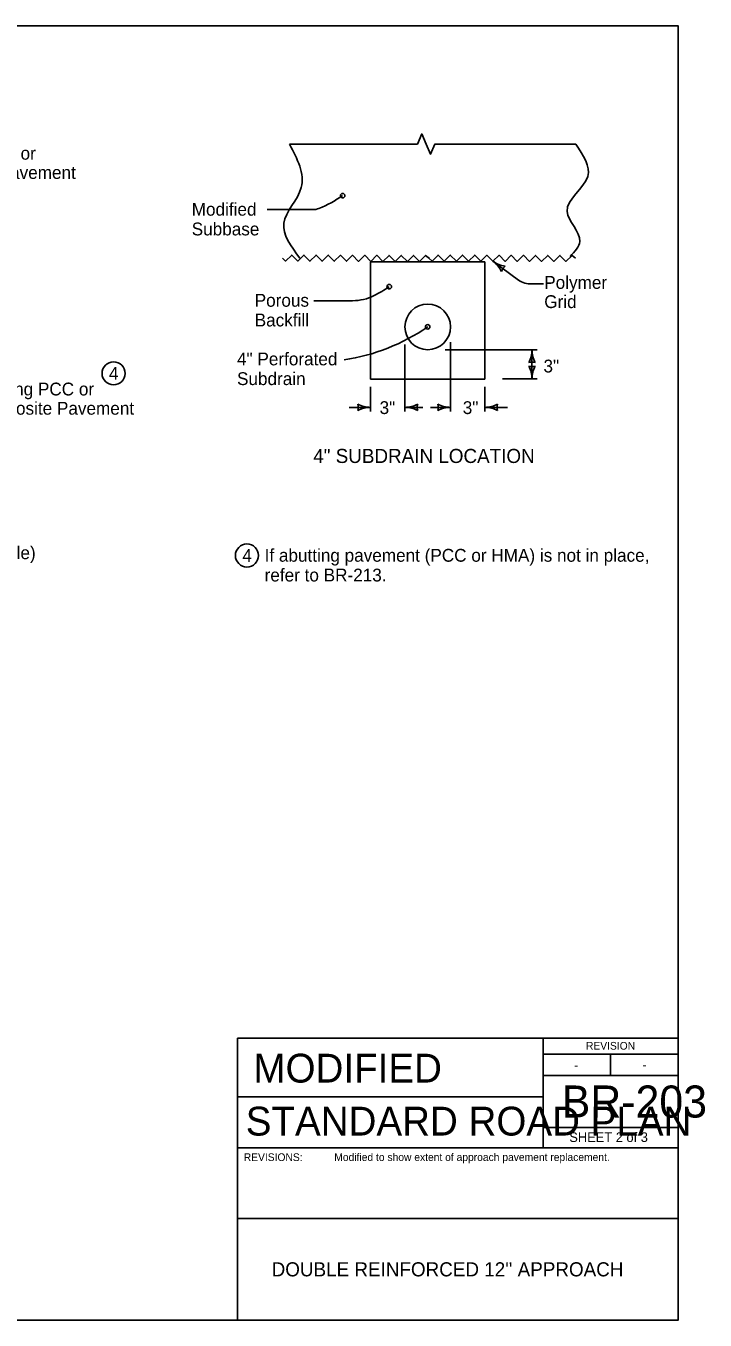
# Model space of a CAD drawing. Extents: x 8925 to 81668, y 4369 to 11918.
# Drawn here: x 15849 to 16910, y 7924 to 9944 of the extents above; entities that cross this region are included whole.
import ezdxf

# ---------------------------------------------------------------- set-up
doc = ezdxf.new("R2010")
doc.units = 0
for name, color, linetype in [('dsnCellElements', 7, 'Continuous'), ('dsnNonPlotable', 7, 'Continuous'), ('dsnShtPlotShapeBatchPrint', 7, 'Continuous'), ('dsnStdBorder', 7, 'Continuous'), ('dsnStdLabel', 7, 'Continuous'), ('Level 1', 7, 'Continuous'), ('Level 3', 7, 'Continuous'), ('Level 5', 7, 'Continuous'), ('SheetBorder', 7, 'Continuous')]:
    doc.layers.add(name, color=color, linetype=linetype)

msp = doc.modelspace()

# ---------------------------------------------------------------- linework, layer by layer
at = {"layer": 'dsnShtPlotShapeBatchPrint'}
for p, q in [((16618.4, 9547), (16578.5, 9576.7)), ((16639, 9541.2), (16657.3, 9541.2)), ((16441, 9446.8), (16441, 9342.1)), ((16504, 9438.6), (16647.5, 9438.6)), ((16512.3, 9450.2), (16512.3, 9342.1)), ((16639.3, 9438.6), (16639.3, 9393)), ((16593.1, 9393), (16647.5, 9393)), ((16387.5, 9380.7), (16387.5, 9342.1)), ((16565.7, 9380.7), (16565.7, 9342.1)), ((16354.2, 9348.6), (16387.5, 9348.6)), ((16441, 9348.6), (16468.9, 9348.6)), ((16481.2, 9348.6), (16512.3, 9348.6)), ((16565.7, 9348.6), (16600.9, 9348.6))]:
    msp.add_line(p, q, dxfattribs=at)
msp.add_arc((16639, 9580.8), 39.6, 238.7046, 270, dxfattribs=at)
at = {"layer": 'dsnStdBorder'}
for p, q in [((16297.3, 9657.2), (16226, 9657.2)), ((16387.5, 9392.6), (16387.5, 9576)), ((16387.5, 9576), (16565.7, 9576)), ((16399.2, 9576), (16565.7, 9576)), ((16565.7, 9392.6), (16565.7, 9576)), ((16359.4, 9515.1), (16298.9, 9515.1)), ((16387.5, 9392.6), (16565.7, 9392.6))]:
    msp.add_line(p, q, dxfattribs=at)
for points in [[(16260.8, 9759.4), (16460.6, 9759.4), (16467.3, 9775.3), (16474.1, 9759.4)], [(16707.8, 9759.4), (16487.7, 9759.4), (16480.9, 9743.6), (16474.1, 9759.4)], [(16250, 9581.6), (16254.8, 9576.8), (16264.3, 9586.3), (16273.8, 9576.8), (16283.3, 9586.3), (16292.8, 9576.7), (16302.3, 9586.2), (16311.8, 9576.7), (16321.3, 9586.2), (16330.8, 9576.6), (16340.4, 9586.1), (16349.8, 9576.6), (16359.4, 9586.1), (16368.8, 9576.5), (16378.4, 9586), (16387.8, 9576.5), (16397.4, 9586), (16406.8, 9576.4), (16416.4, 9585.9), (16425.8, 9576.4), (16435.4, 9585.9), (16444.9, 9576.3), (16454.4, 9585.8), (16463.9, 9576.3), (16473.4, 9585.8), (16479.2, 9581.2)], [(16478.6, 9581.6), (16483.3, 9576.8), (16492.9, 9586.3), (16502.4, 9576.8), (16511.9, 9586.3), (16521.4, 9576.7), (16530.9, 9586.2), (16540.4, 9576.7), (16549.9, 9586.2), (16559.4, 9576.6), (16568.9, 9586.1), (16578.4, 9576.6), (16587.9, 9586.1), (16597.4, 9576.5), (16606.9, 9586), (16616.4, 9576.5), (16625.9, 9586), (16635.4, 9576.4), (16644.9, 9585.9), (16654.4, 9576.4), (16664, 9585.9), (16673.4, 9576.3), (16683, 9585.8), (16692.4, 9576.3), (16702, 9585.8), (16707.2, 9581.6)]]:
    msp.add_lwpolyline(points, dxfattribs=at)
for centre, radius in [((16476.6, 9474.2), 35.6), ((15986.4, 9401.7), 18), ((16194.5, 9117.4), 18)]:
    msp.add_circle(centre, radius, dxfattribs=at)
for centre, radius, start, end in [((16230.3, 9844.8), 200.9, 292.4048, 304.4007), ((16297.3, 9682.2), 25, 270, 292.4048), ((16303.1, 9702.7), 200.9, 296.5518, 304.4007), ((16359.4, 9590.1), 75, 270, 296.5518), ((16299, 9733.6), 314.4, 278.602, 304.4007), ((16596.8, 9438.6), 42.5, 331.9275, 360), ((16681.8, 9438.6), 42.5, 180, 208.0725), ((16639.3, 9402.9), 16.4, 72.2666, 107.7334), ((16639.3, 9428.7), 16.4, 252.2666, 287.7333), ((16596.8, 9393), 42.5, 360, 28.0725), ((16681.8, 9393), 42.5, 151.9275, 180), ((16351.9, 9348.6), 16.4, 342.2666, 17.7333), ((16387.5, 9391.1), 42.5, 241.9275, 270), ((16441, 9391.1), 42.5, 270, 298.0725), ((16441, 9391.1), 42.5, 270, 298.0725), ((16476.6, 9348.6), 16.4, 162.2666, 197.7334), ((16476.6, 9348.6), 16.4, 162.2666, 197.7334), ((16476.6, 9348.6), 16.4, 342.2666, 17.7333), ((16512.3, 9391.1), 42.5, 241.9275, 270), ((16476.6, 9348.6), 16.4, 342.2666, 17.7333), ((16512.3, 9391.1), 42.5, 241.9275, 270), ((16565.7, 9391.1), 42.5, 270, 298.0725), ((16601.3, 9348.6), 16.4, 162.2666, 197.7334), ((16387.5, 9306.1), 42.5, 90, 118.0725), ((16441, 9306.1), 42.5, 61.9275, 90), ((16441, 9306.1), 42.5, 61.9275, 90), ((16512.3, 9306.1), 42.5, 90, 118.0725), ((16512.3, 9306.1), 42.5, 90, 118.0725), ((16565.7, 9306.1), 42.5, 61.9275, 90)]:
    msp.add_arc(centre, radius, start, end, dxfattribs=at)
for points in [[(16260.8, 9759.4), (16279.3, 9691.6), (16252.1, 9636), (16276.8, 9581.6)], [(16707.8, 9759.4), (16726.3, 9708.9), (16694.2, 9654.5), (16713.9, 9607.6), (16699.1, 9584.1)]]:
    msp.add_spline(points, degree=3, dxfattribs=at)
at = {"layer": 'Level 1'}
for p, q in [((16656.6, 8364), (16656.6, 8272.7)), ((16656.6, 8339.1), (16867.5, 8339.1)), ((16762.1, 8339.1), (16762.1, 8305.9)), ((16656.6, 8305.9), (16867.5, 8305.9)), ((16179.5, 8272.7), (16656.6, 8272.7)), ((16656.6, 8272.7), (16656.6, 8192.7)), ((16867.5, 8224.9), (16656.6, 8224.9)), ((16179.5, 8192.7), (16867.5, 8192.7)), ((16179.5, 8082.7), (16867.5, 8082.7))]:
    msp.add_line(p, q, dxfattribs=at)
msp.add_lwpolyline([(16179.5, 8364), (16867.5, 8364), (16867.5, 7924), (16179.5, 7924)], close=True, dxfattribs=at)
at = {"layer": 'Level 3'}
for centre, radius, start, end in [((16553.1, 9542.7), 42.5, 25.1788, 53.2513), ((16604, 9610.8), 42.5, 233.2513, 261.3238), ((16607.1, 9555.4), 16.4, 125.5179, 160.9846)]:
    msp.add_arc(centre, radius, start, end, dxfattribs=at)
at = {"layer": 'Level 5'}
for centre in [(16343.8, 9679), (16416.6, 9536.9), (16476.6, 9474.2)]:
    msp.add_circle(centre, 3.54, dxfattribs=at)
at = {"layer": 'SheetBorder'}
msp.add_lwpolyline([(13732.5, 9944), (16867.5, 9944), (16867.5, 7924), (13732.5, 7924)], close=True, dxfattribs=at)

# ---------------------------------------------------------------- texts
at = {"layer": 'dsnCellElements'}
msp.add_text('MODIFIED', height=45, dxfattribs=at).set_placement((16204.6, 8294.8))
at = {"layer": 'dsnNonPlotable'}
msp.add_text('REVISIONS:', height=12, dxfattribs=at).set_placement((16189.5, 8172.3))
at = {"layer": 'dsnShtPlotShapeBatchPrint'}
for s, p in [('Abutting PCC or', (15671.7, 9735.2)), ('Composite Pavement', (15671.7, 9705.2)), ('Modified', (16108.3, 9647.8)), ('Subbase', (16108.3, 9617)), ('Polymer ', (16658.5, 9533.6)), ('Porous', (16206.6, 9505.7)), ('Grid', (16658.5, 9503.6)), ('Backfill', (16206.6, 9474.9)), ('4" Perforated ', (16179, 9414.2)), ('3"', (16657.3, 9403.1)), ('4', (15979.1, 9391.7)), ('Subdrain', (16179, 9383.4)), ('Abutting PCC or', (15762.7, 9367.2)), ('Composite Pavement', (15762.7, 9337.2)), ('3"', (16401.5, 9338.2)), ('3"', (16531.3, 9338.2)), ('(if applicable)', (15705.7, 9111.7))]:
    msp.add_text(s, height=20, dxfattribs=at).set_placement(p)
at = {"layer": 'dsnStdBorder'}
for s, height, p in [('4" SUBDRAIN LOCATION', 22, (16298, 9261.8)), ('4', 20, (16187.3, 9107.4))]:
    msp.add_text(s, height=height, dxfattribs=at).set_placement(p)
at = {"layer": 'dsnStdLabel'}
for s, p in [('If abutting pavement (PCC or HMA) is not in place, ', (16222.1, 9107.7)), ('refer to BR-213.', (16222.1, 9076.9))]:
    msp.add_text(s, height=20, dxfattribs=at).set_placement(p)
at = {"layer": 'Level 1'}
for s, height, p in [('REVISION', 12, (16723.6, 8346.2)), ('-', 15, (16705.1, 8314.7)), ('-', 15, (16811.6, 8315.1)), ('BR-203', 50, (16685.8, 8240.2)), ('STANDARD ROAD PLAN', 45.001, (16192.6, 8212.1)), ('SHEET 2 of 3', 15, (16697.6, 8202)), ('Modified to show extent of approach pavement replacement.', 12, (16330.8, 8172.4)), ("DOUBLE REINFORCED 12'' APPROACH", 22, (16233, 7992.3))]:
    msp.add_text(s, height=height, dxfattribs=at).set_placement(p)

doc.saveas('drawing.dxf')
